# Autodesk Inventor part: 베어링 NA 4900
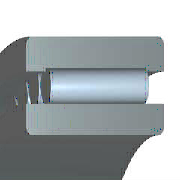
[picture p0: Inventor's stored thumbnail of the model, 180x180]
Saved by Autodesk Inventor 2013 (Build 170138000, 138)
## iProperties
Created: 2021-07
Part Number: 베어링 NA 4900
Material: 강철, 연강
Description: 니들 롤러 베어링 - 경계 치수 및 공차
Document SubType Name: Modeling
Standard: KS B 2029
Designer: mdu
Standards Organization: KS
Language: ko-KR
Size Designation: NA 4900 - 10 x 22 x 13
Categories: <MemberInstance><Categories><Category DisplayName="샤프트 부품" InternalName="7f7aeb1f-a693-4053-b835-cee3144e0d98" Mnemonic="SHFT"><Category DisplayName="베어링" Inter
Density: 7.86 g/cm^3
Mass: 23.8214 g
Surface Area: 38.613 cm^2
Volume: 3.03071 cm^3
IsCustomPart: 0
Author: mdu
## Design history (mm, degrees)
sketch "스케치"
  geometry: L1 (1.857, 9)-(11.143, 9); L2 (11.143, 9)-(11.143, 7); L3 (13, 7)-(0, 7); L4 (1.857, 7)-(1.857, 9); L5 (1.857, 8)-(11.143, 8); L6 (6.5, 8)-(6.5, 7); L7 (0, 5)-(13, 5); L8 (0, 11)-(13, 11); L9 (13, 5)-(13, 7); L10 (13, 8.8)-(13, 11); L11 (1.857, 8.8)-(0, 8.8); L12 (11.143, 8.8)-(13, 8.8); L13 (-6, 0)-(36, 0) reference; L14 (0, -1.9)-(0, 14.9) reference
  constraints: 24 end point, 8 point on line, 3 midpoint, 3 parallel, 3 perpendicular, 2 symmetric about line, 1 horizontal, 1 other
  dimensions: "d6" = 10 diameter of L7 L13 (= WD); "d7" = 14 diameter of L3 L13 (= KID1); "d8" = 22 diameter of L8 L13 (= BD); "d9" = 16 diameter of L6.start L13 (= 0.5 x WD + 0.5 x BD); "d10" = 17.6 diameter of L12 L13 (= 0.9 x BD + 0.9 x WD - 0.8 x KID1); "d11" = 18 diameter of L1 L13 (= BD + WD - KID1); "d12" = 1.85714 distance between parallel lines of L14 L4 (= 0.142857 x KB); "d13" = 13 distance between parallel lines of L14 L9 (= KB); "d14" = 11.14286 distance between parallel lines of L14 L2 (= 0.857143 x KB)
revolve "본체" stored, may be unused: angle "d17" = 90 deg
revolve "롤러" stored, may be unused: angle "d18" = 90 deg
pattern_circular "IDS_ARRAYROLLER[SIMPL:T]" dims angle "d2" = 360 deg
body "Solid1"
fillet "모깎기1" dims "d0" = 0.3 (= KRS)
other parameters: "WD" = 10 [user parameter; used in 6 equation terms], "BD" = 22 [user parameter; used in 6 equation terms], "KB" = 13 [user parameter; used in 3 equation terms], "KID1" = 14 [user parameter; used in 4 equation terms], "KRS" = 0.3 [user parameter; used in 1 equation term], "d3" = 0, "d4" = 0, "d5" = 0, "d15" = 0, "d16" = 0, "BC0" = 9150000 [user parameter], "WR" = 5 (= 0.5 x WD) [user parameter], "BBA" = 0 [user parameter], "BC" = 8150000 [user parameter], "BR" = 11 (= 0.5 x BD) [user parameter]
